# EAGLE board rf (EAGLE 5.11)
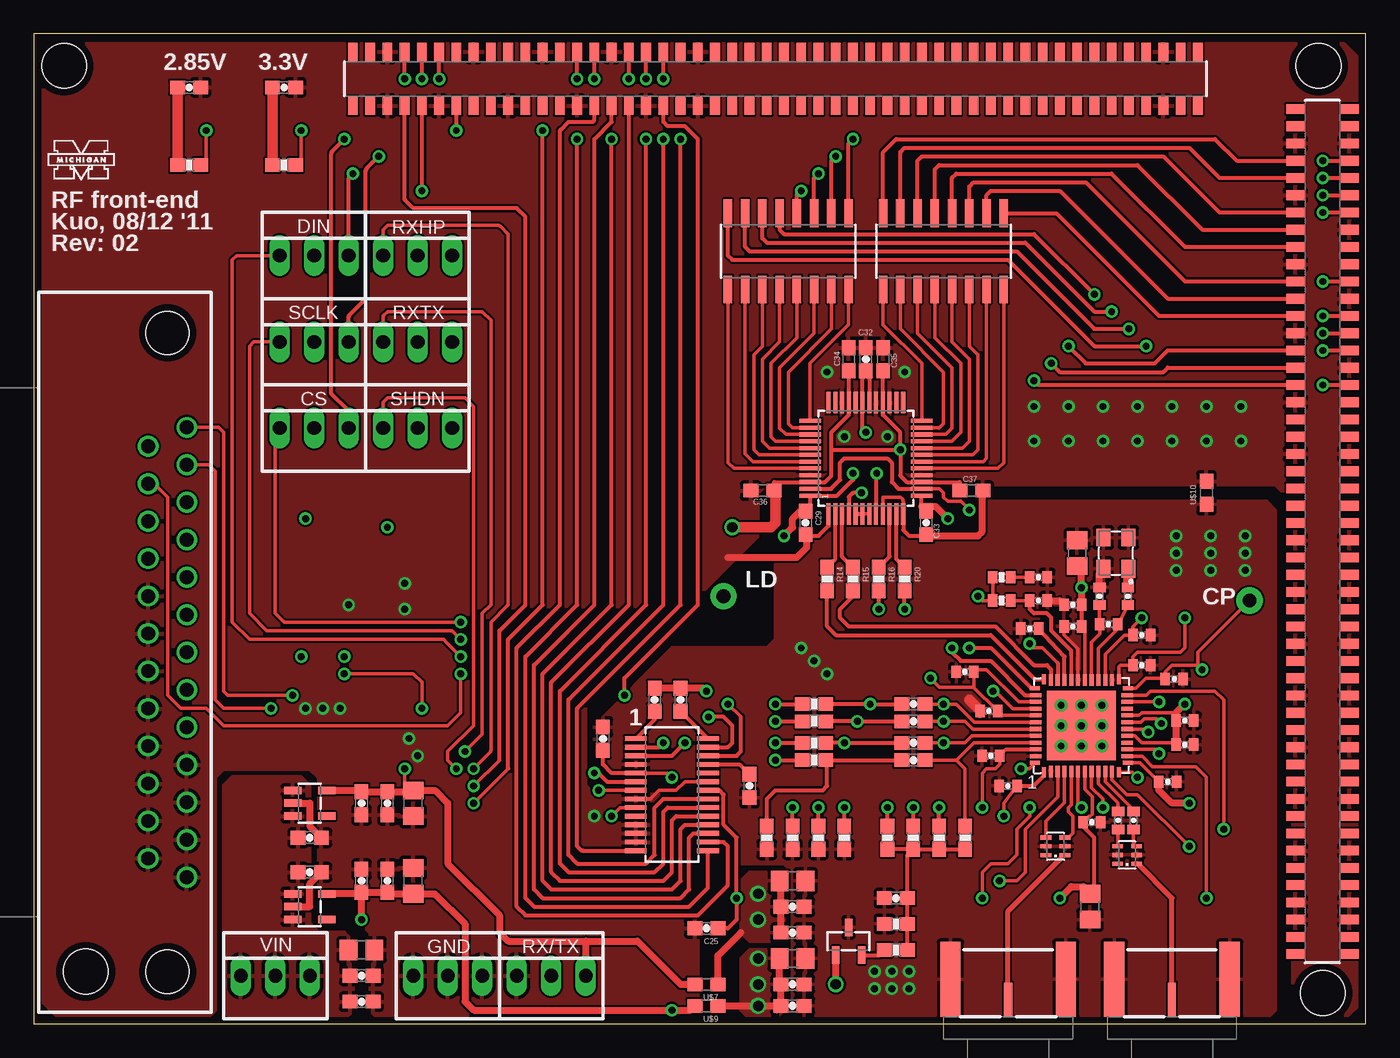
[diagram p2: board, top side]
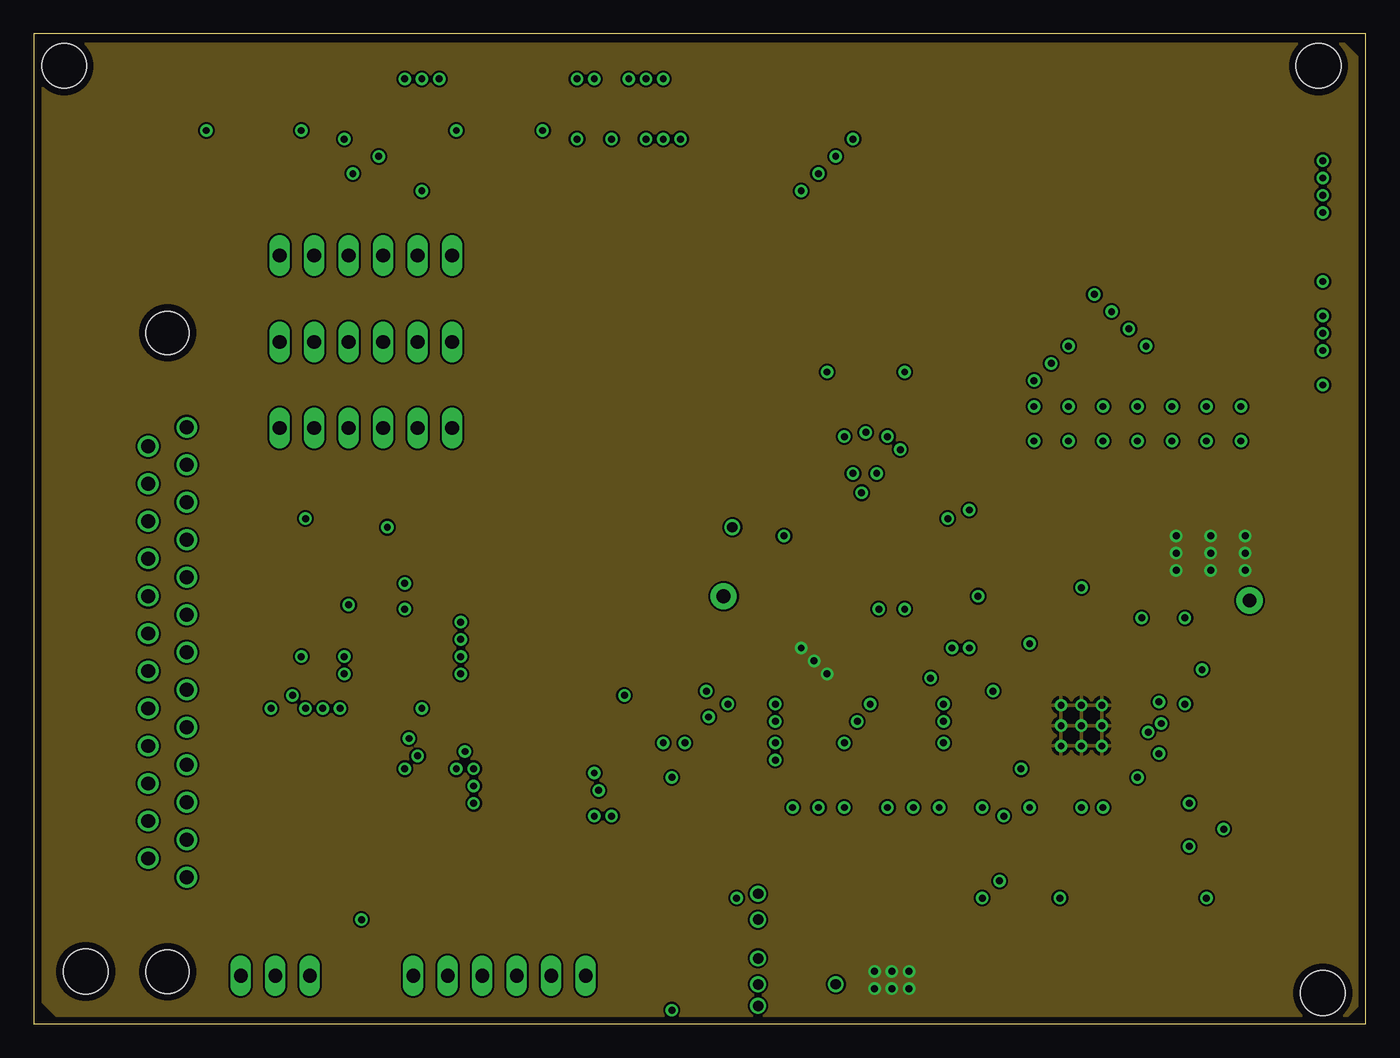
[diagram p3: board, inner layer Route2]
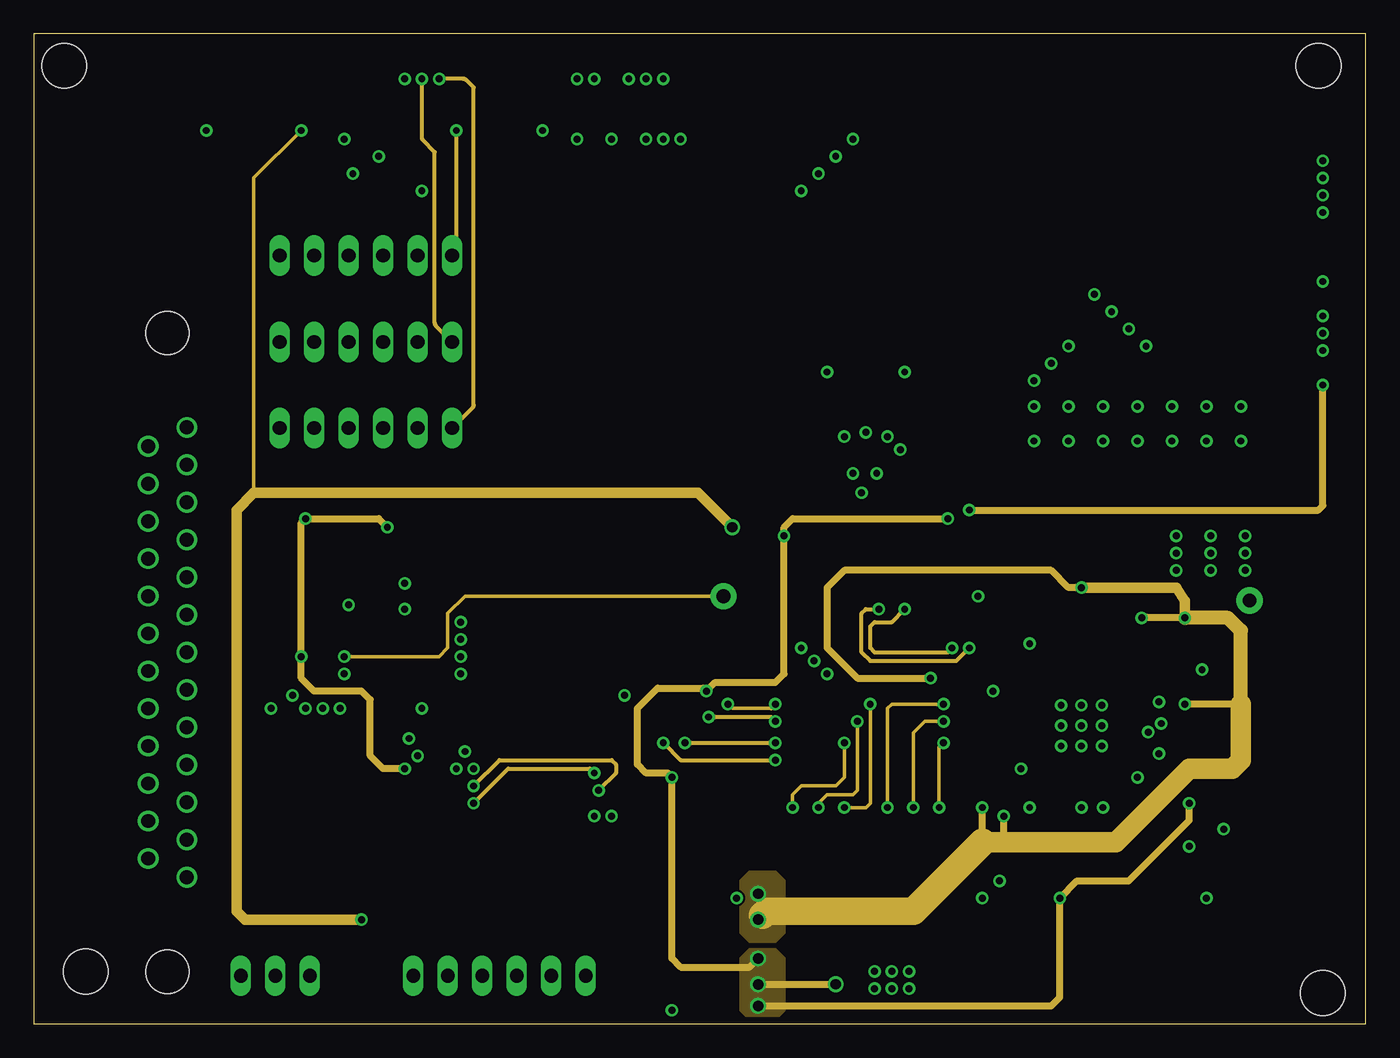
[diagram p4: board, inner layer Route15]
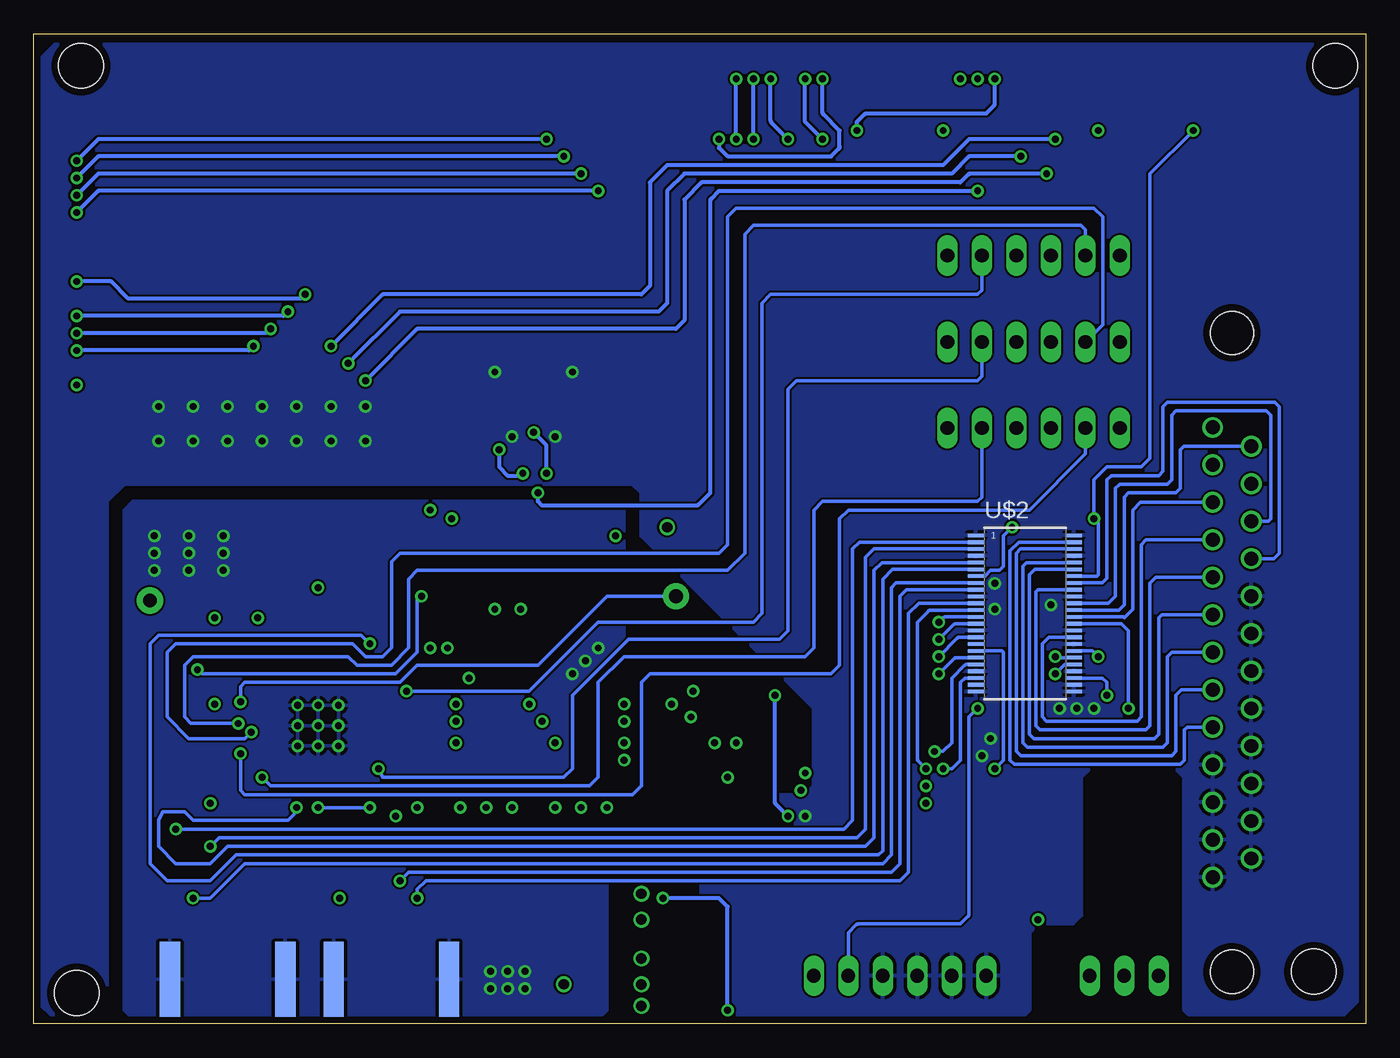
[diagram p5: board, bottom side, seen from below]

Size 98.08 x 72.87 mm. Coordinates in mm from the lower left corner, seen from the top.
Outline: 0,0 98.08,0 98.08,72.87 0,72.87 0,0
Copper layers (1+2*15+16): Top 0.0178mm / dielectric 0.3048mm / Route2 0.0356mm / dielectric 0.7112mm / Route15 0.0356mm / dielectric 0.3048mm / Bottom 0.0178mm
Design rules "SSC-EAGLE-4Lyr_v1.0.0.3 *": minimum track width 6mil, minimum drill 8mil, track to track 6mil, track to pad 6mil, pad to pad 6mil, via to via 6mil, smd to smd 6mil, copper to edge 20mil, drill to drill 16mil, minimum pad ring 8mil, minimum via ring 8mil, stop-mask expansion 3mil, vias tented up to drill 0mil, thermal gap 10mil

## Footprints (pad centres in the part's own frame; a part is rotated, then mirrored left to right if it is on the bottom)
0402-CAP = smd 0.7 x 0.9: 1 -0.65,0; 2 0.65,0
C0805 = smd 1.3 x 1.5: 1 -0.95,0; 2 0.95,0
0603-CAP = smd 1.1 x 1: 1 -0.85,0; 2 0.85,0
C0603 = smd 1.1 x 1: 1 -0.85,0; 2 0.85,0
22-23-2031 = drill 1 long: 1 -2.54,0; 2 0,0; 3 2.54,0
STAND-OFF = hole 3.302: 0,0
CLP-150 = smd 0.711 x 1.35: P$1 -31.115,1.99; P$2 -31.115,-1.99; P$3 -29.845,1.99; P$4 -29.845,-1.99; P$5 -28.575,1.99; P$6 -28.575,-1.99; P$7 -27.305,1.99; P$8 -27.305,-1.99; P$9 -26.035,1.99; P$10 -26.035,-1.99; P$11 -24.765,1.99; P$12 -24.765,-1.99; P$13 -23.495,1.99; P$14 -23.495,-1.99; P$15 -22.225,1.99; P$16 -22.225,-1.99; P$17 -20.955,1.99; P$18 -20.955,-1.99; P$19 -19.685,1.99; P$20 -19.685,-1.99; P$21 -18.415,1.99; P$22 -18.415,-1.99; P$23 -17.145,1.99; P$24 -17.145,-1.99; P$25 -15.875,1.99; P$26 -15.875,-1.99; P$27 -14.605,1.99; P$28 -14.605,-1.99; P$29 -13.335,1.99; P$30 -13.335,-1.99; P$31 -12.065,1.99; P$32 -12.065,-1.99; P$33 -10.795,1.99; P$34 -10.795,-1.99; P$35 -9.525,1.99; P$36 -9.525,-1.99; P$37 -8.255,1.99; P$38 -8.255,-1.99; P$39 -6.985,1.99; P$40 -6.985,-1.99; P$41 -5.715,1.99; P$42 -5.715,-1.99; P$43 -4.445,1.99; P$44 -4.445,-1.99; P$45 -3.175,1.99; P$46 -3.175,-1.99; P$47 -1.905,1.99; P$48 -1.905,-1.99; P$49 -0.635,1.99; P$50 -0.635,-1.99; P$51 0.635,1.99; P$52 0.635,-1.99; P$53 1.905,1.99; P$54 1.905,-1.99; P$55 3.175,1.99; P$56 3.175,-1.99; P$57 4.445,1.99; P$58 4.445,-1.99; P$59 5.715,1.99; P$60 5.715,-1.99; P$61 6.985,1.99; P$62 6.985,-1.99; P$63 8.255,1.99; P$64 8.255,-1.99; P$65 9.525,1.99; P$66 9.525,-1.99; P$67 10.795,1.99; P$68 10.795,-1.99; P$69 12.065,1.99; P$70 12.065,-1.99; P$71 13.335,1.99; P$72 13.335,-1.99; P$73 14.605,1.99; P$74 14.605,-1.99; P$75 15.875,1.99; P$76 15.875,-1.99; P$77 17.145,1.99; P$78 17.145,-1.99; P$79 18.415,1.99; P$80 18.415,-1.99; P$81 19.685,1.99; P$82 19.685,-1.99; P$83 20.955,1.99; P$84 20.955,-1.99; P$85 22.225,1.99; P$86 22.225,-1.99; P$87 23.495,1.99; P$88 23.495,-1.99; P$89 24.765,1.99; P$90 24.765,-1.99; P$91 26.035,1.99; P$92 26.035,-1.99; P$93 27.305,1.99; P$94 27.305,-1.99; P$95 28.575,1.99; P$96 28.575,-1.99; P$97 29.845,1.99; P$98 29.845,-1.99; P$99 31.115,1.99; P$100 31.115,-1.99
0402-RES = smd 0.7 x 0.9: 1 -0.65,0; 2 0.65,0
0603-RES = smd 1.1 x 1: 1 -0.85,0; 2 0.85,0
BALUN = smd 0.8 x 0.3: P$1 -0.7,0.65; P$2 -0.7,0; P$3 -0.7,-0.65; P$4 0.7,-0.65; P$5 0.7,0; P$6 0.7,0.65
SOT-5 = smd 1.3 x 0.55: P$1 -1.25,0.95; P$2 -1.25,0; P$3 -1.25,-0.95; P$4 1.25,-0.95; P$5 1.25,0.95
TQFN-48 = smd 5.1 x 5.1: EP 0,0 | smd 0.3 x 0.75: P$1 -2.75,-3.425; P$12 2.75,-3.425; P$25 2.75,3.425; P$36 -2.75,3.425 | smd 0.3 x 0.85: P$2 -2.25,-3.375; P$3 -1.75,-3.375; P$4 -1.25,-3.375; P$5 -0.75,-3.375; P$6 -0.25,-3.375; P$7 0.25,-3.375; P$8 0.75,-3.375; P$9 1.25,-3.375; P$10 1.75,-3.375; P$11 2.25,-3.375; P$26 2.25,3.375; P$27 1.75,3.375; P$28 1.25,3.375; P$29 0.75,3.375; P$30 0.25,3.375; P$31 -0.25,3.375; P$32 -0.75,3.375; P$33 -1.25,3.375; P$34 -1.75,3.375; P$35 -2.25,3.375 | smd 0.75 x 0.3: P$13 3.425,-2.75; P$24 3.425,2.75; P$37 -3.425,2.75; P$48 -3.425,-2.75 | smd 0.85 x 0.3: P$14 3.375,-2.25; P$15 3.375,-1.75; P$16 3.375,-1.25; P$17 3.375,-0.75; P$18 3.375,-0.25; P$19 3.375,0.25; P$20 3.375,0.75; P$21 3.375,1.25; P$22 3.375,1.75; P$23 3.375,2.25; P$38 -3.375,2.25; P$39 -3.375,1.75; P$40 -3.375,1.25; P$41 -3.375,0.75; P$42 -3.375,0.25; P$43 -3.375,-0.25; P$44 -3.375,-0.75; P$45 -3.375,-1.25; P$46 -3.375,-1.75; P$47 -3.375,-2.25 | drill 0.5 round: P$49 0,0; P$50 0,1.5; P$51 1.5,1.5; P$52 1.5,0; P$53 -1.5,1.5; P$54 -1.5,0; P$55 0,-1.5; P$56 1.5,-1.5; P$57 -1.5,-1.5
TSSOP-48 = smd 1.2 x 0.27: P$1 -3.6,5.75; P$2 -3.6,5.25; P$3 -3.6,4.75; P$4 -3.6,4.25; P$5 -3.6,3.75; P$6 -3.6,3.25; P$7 -3.6,2.75; P$8 -3.6,2.25; P$9 -3.6,1.75; P$10 -3.6,1.25; P$11 -3.6,0.75; P$12 -3.6,0.25; P$13 -3.6,-0.25; P$14 -3.6,-0.75; P$15 -3.6,-1.25; P$16 -3.6,-1.75; P$17 -3.6,-2.25; P$18 -3.6,-2.75; P$19 -3.6,-3.25; P$20 -3.6,-3.75; P$21 -3.6,-4.25; P$22 -3.6,-4.75; P$23 -3.6,-5.25; P$24 -3.6,-5.75; P$25 3.6,-5.75; P$26 3.6,-5.25; P$27 3.6,-4.75; P$28 3.6,-4.25; P$29 3.6,-3.75; P$30 3.6,-3.25; P$31 3.6,-2.75; P$32 3.6,-2.25; P$33 3.6,-1.75; P$34 3.6,-1.25; P$35 3.6,-0.75; P$36 3.6,-0.25; P$37 3.6,0.25; P$38 3.6,0.75; P$39 3.6,1.25; P$40 3.6,1.75; P$41 3.6,2.25; P$42 3.6,2.75; P$43 3.6,3.25; P$44 3.6,3.75; P$45 3.6,4.25; P$46 3.6,4.75; P$47 3.6,5.25; P$48 3.6,5.75
SMA-SMD = smd 1.5 x 5.5: P$1 -4.25,-0.375; P$2 4.25,-0.375 | smd 1.5 x 5.5 bottom: P$3 4.25,-0.375; P$4 -4.25,-0.375 | smd 0.6 x 2.5: SIGNAL 0,1.125
CX3225SB = smd 1.3 x 1.05: GND 1.15,-0.925; GND2 -1.15,0.925; HOT -1.15,-0.925; HOT2 1.15,0.925
QSOP = smd 1.6 x 0.356: P$1 -2.655,4.128; P$2 -2.655,3.493; P$3 -2.655,2.857; P$4 -2.655,2.223; P$5 -2.655,1.587; P$6 -2.655,0.953; P$7 -2.655,0.318; P$8 -2.655,-0.318; P$9 -2.655,-0.953; P$10 -2.655,-1.587; P$11 -2.655,-2.223; P$12 -2.655,-2.857; P$13 -2.655,-3.493; P$14 -2.655,-4.128; P$15 2.655,-4.128; P$16 2.655,-3.493; P$17 2.655,-2.857; P$18 2.655,-2.223; P$19 2.655,-1.587; P$20 2.655,-0.953; P$21 2.655,-0.318; P$22 2.655,0.318; P$23 2.655,0.953; P$24 2.655,1.587; P$25 2.655,2.223; P$26 2.655,2.857; P$27 2.655,3.493; P$28 2.655,4.128
0603 = smd 1.1 x 1: 1 -0.85,0; 2 0.85,0
SOT-3 = smd 0.55 x 1.28: P$1 -0.95,-1.015; P$2 0.95,-1.015; P$3 0,1.015
SOIC-16 = smd 2.03 x 0.63: P$1 -2.8,4.445; P$2 -2.8,3.175; P$3 -2.8,1.905; P$4 -2.8,0.635; P$5 -2.8,-0.635; P$6 -2.8,-1.905; P$7 -2.8,-3.175; P$8 -2.8,-4.445; P$9 2.8,-4.445; P$10 2.8,-3.175; P$11 2.8,-1.905; P$12 2.8,-0.635; P$13 2.8,0.635; P$14 2.8,1.905; P$15 2.8,3.175; P$16 2.8,4.445
LQFP(ST-48) = smd 1.6 x 0.3: P$1 -4.1,2.75; P$2 -4.1,2.25; P$3 -4.1,1.75; P$4 -4.1,1.25; P$5 -4.1,0.75; P$6 -4.1,0.25; P$7 -4.1,-0.25; P$8 -4.1,-0.75; P$9 -4.1,-1.25; P$10 -4.1,-1.75; P$11 -4.1,-2.25; P$12 -4.1,-2.75; P$25 4.1,-2.75; P$26 4.1,-2.25; P$27 4.1,-1.75; P$28 4.1,-1.25; P$29 4.1,-0.75; P$30 4.1,-0.25; P$31 4.1,0.25; P$32 4.1,0.75; P$33 4.1,1.25; P$34 4.1,1.75; P$35 4.1,2.25; P$36 4.1,2.75 | smd 0.3 x 1.6: P$13 -2.75,-4.1; P$14 -2.25,-4.1; P$15 -1.75,-4.1; P$16 -1.25,-4.1; P$17 -0.75,-4.1; P$18 -0.25,-4.1; P$19 0.25,-4.1; P$20 0.75,-4.1; P$21 1.25,-4.1; P$22 1.75,-4.1; P$23 2.25,-4.1; P$24 2.75,-4.1; P$37 2.75,4.1; P$38 2.25,4.1; P$39 1.75,4.1; P$40 1.25,4.1; P$41 0.75,4.1; P$42 0.25,4.1; P$43 -0.25,4.1; P$44 -0.75,4.1; P$45 -1.25,4.1; P$46 -1.75,4.1; P$47 -2.25,4.1; P$48 -2.75,4.1
DB25 = drill 1.02 round: P$1 -16.56,1.42; P$2 -13.8,1.42; P$3 -11.04,1.42; P$4 -8.28,1.42; P$5 -5.52,1.42; P$6 -2.76,1.42; P$7 0,1.42; P$8 2.76,1.42; P$9 5.52,1.42; P$10 8.28,1.42; P$11 11.04,1.42; P$12 13.8,1.42; P$13 16.56,1.42; P$14 -15.18,-1.42; P$15 -12.42,-1.42; P$16 -9.66,-1.42; P$17 -6.9,-1.42; P$18 -4.14,-1.42; P$19 -1.38,-1.42; P$20 1.38,-1.42; P$21 4.14,-1.42; P$22 6.9,-1.42; P$23 9.66,-1.42; P$24 12.42,-1.42; P$25 15.18,-1.42 | hole 3.18: -23.52,0; 23.52,0

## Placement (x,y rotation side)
C1  100p  [0402-CAP]  71.75,17.5 180 top
C2  100p  [0402-CAP]  77.91,14.83 0 top
C3  10u  [C0805]  77.79,8.61 270 top
C4  1.5p  [0402-CAP]  79.85,14.96 270 top
C5  1.5p  [0402-CAP]  80.99,14.96 270 top
C6  100p  [0402-CAP]  83.5,17.82 0 top
C7  100p  [0402-CAP]  84.77,20.55 0 top
C8  10n  [0402-CAP]  84.77,22.33 0 top
C9  10n  [0402-CAP]  81.6,26.39 0 top
C10  10n  [0402-CAP]  81.6,28.61 0 top
C11  100p  [0402-CAP]  76.52,29.25 180 top
C12  100n  [0402-CAP]  76.52,30.84 180 top
C13  10u  [C0805]  76.83,34.65 270 top
C14  10n  [0402-CAP]  68.58,25.91 180 top
C15  10n  [0402-CAP]  70.33,23.03 180 top
C16  100p  [0402-CAP]  70.48,19.72 180 top
C17  68p  [0402-CAP]  73.98,31.15 180 top
C18  2.2n  [0402-CAP]  73.98,32.87 180 top
C19  100p  [0402-CAP]  83.98,25.37 0 top
C20  33p  [0402-CAP]  79.15,29.41 0 top
C21  18p  [0402-CAP]  78.49,31.47 90 top
C22  1n  [0402-CAP]  80.58,31.47 90 top
C23  100n  [0402-CAP]  73.34,29.09 180 top
C24  0.1u  [0603-CAP]  52.7,17.5 270 top
C25  0.1u  [0603-CAP]  49.53,7.02 180 top
C26  10u  [C0805]  55.88,10.52 0 top
C27  0.1u  [0603-CAP]  26.04,10.52 90 top
C28  0.1u  [0603-CAP]  41.91,20.99 270 top
C29  0.1u  [0603-CAP]  56.83,36.87 270 top
C30  0.1u  [0603-CAP]  47.62,23.85 270 top
C31  1u  [0603-CAP]  24.13,10.52 90 top
C32  0.1u  [0603-CAP]  61.28,48.93 90 top
C33  0.1u  [0603-CAP]  65.72,36.87 270 top
C34  0.1u  [C0603]  60.01,48.93 90 top
C35  0.1u  [C0603]  62.55,48.93 90 top
C36  0.1u  [C0603]  53.66,39.25 180 top
C37  0.1u  [C0603]  69.06,39.25 0 top
C38  0.01u  [0603-CAP]  64.77,22.26 0 top
C39  0.1u  [0603-CAP]  24.13,16.23 270 top
C40  1u  [0603-CAP]  26.04,16.23 270 top
C41  10u  [C0805]  24.13,5.44 0 top
C42  0.1u  [0603-CAP]  45.72,23.85 270 top
C43  0.1u  [0603-CAP]  63.5,9.25 180 top
C44  0.01u  [0603-CAP]  64.77,23.53 0 top
C45  0.01u  [0603-CAP]  64.77,19.41 180 top
C46  0.01u  [0603-CAP]  64.77,20.68 180 top
C47  10u  [C0805]  27.94,16.23 270 top
C48  10u  [C0805]  55.88,4.8 0 top
C49  10u  [C0805]  27.94,10.52 90 top
C50  0.1u  [0603-CAP]  18.41,68.94 0 top
C51  0.1u  [0603-CAP]  11.43,68.94 0 top
C72  0.1u  [0603-CAP]  24.13,3.53 0 top
C73  1u  [0603-CAP]  24.13,1.63 0 top
C74  0.1u  [0603-CAP]  20.32,11.15 0 top
C75  0.1u  [0603-CAP]  20.32,13.69 0 top
C78  0.1u  [0603-CAP]  55.88,1.31 0 top
C79  1u  [0603-CAP]  55.88,2.9 0 top
C80  0.1u  [0603-CAP]  55.88,8.61 0 top
C81  1u  [0603-CAP]  55.88,6.71 0 top
CS  22-23-2031  [22-23-2031]  20.64,43.85 0 top
DIN  22-23-2031  [22-23-2031]  20.64,56.55 0 top
GND  22-23-2031  [22-23-2031]  30.48,3.53 0 top
JP4  STAND-OFF  [STAND-OFF]  2.22,70.52 0 top
JP5  STAND-OFF  [STAND-OFF]  3.81,3.85 0 top
JP6  STAND-OFF  [STAND-OFF]  94.61,70.52 0 top
JP7  STAND-OFF  [STAND-OFF]  94.93,2.26 0 top
P1  DEV_CLP-150  [CLP-150]  54.61,69.57 0 top
P2  DEV_CLP-150  [CLP-150]  94.91,36.23 270 top
R1  750  [0402-RES]  71.28,31.15 180 top
R2  1.2k  [0402-RES]  71.28,32.87 0 top
R3  75  [0603-RES]  57.47,22.26 0 top
R4  75  [0603-RES]  57.78,13.69 90 top
R5  75  [0603-RES]  57.47,23.53 180 top
R6  75  [0603-RES]  59.69,13.69 90 top
R7  75  [0603-RES]  57.47,19.41 0 top
R8  75  [0603-RES]  57.47,20.68 0 top
R9  75  [0603-RES]  55.88,13.69 90 top
R10  75  [0603-RES]  53.98,13.69 90 top
R11  3.3k  [0603-RES]  64.77,13.69 270 top
R12  270  [0603-RES]  63.5,5.44 0 top
R13  1k  [0603-RES]  63.5,7.34 0 top
R14  0  [0603-RES]  58.42,32.74 270 top
R15  0  [0603-RES]  60.33,32.74 270 top
R16  0  [0603-RES]  62.23,32.74 270 top
R17  3.3k  [0603-RES]  62.87,13.69 270 top
R18  3.3k  [0603-RES]  68.58,13.69 270 top
R19  3.3k  [0603-RES]  66.67,13.69 270 top
R20  0  [0603-RES]  64.14,32.74 270 top
R21  3.3k  [0603-RES]  18.41,63.22 0 top
R22  3.3k  [0603-RES]  11.43,63.22 0 top
RX/TX  22-23-2031  [22-23-2031]  38.1,3.53 0 top
RXHP  22-23-2031  [22-23-2031]  28.26,56.55 0 top
RXTX  22-23-2031  [22-23-2031]  28.26,50.2 0 top
SCLK  22-23-2031  [22-23-2031]  20.64,50.2 0 top
SHDN  22-23-2031  [22-23-2031]  28.26,43.85 0 top
T1  TDK_CHIP_BALUN  [BALUN]  75.25,13.06 180 top
T2  TDK_CHIP_BALUN  [BALUN]  80.52,12.42 180 top
U1  REG102  [SOT-5]  20.32,16.23 0 top
U2  REG102  [SOT-5]  20.32,8.61 0 top
U$1  MAX2831  [TQFN-48]  77.15,21.95 0 top
U$2  SN74LVTH16244A  [TSSOP-48]  25.08,30.2 0 bottom
U$3  J658-ND  [SMA-SMD]  71.75,2.9 180 top
U$4  J658-ND  [SMA-SMD]  83.82,2.9 180 top
U$5  CX3225SB  [CX3225SB]  79.69,34.65 90 top
U$6  MAX5189BEEI+  [QSOP]  46.99,16.87 0 top
U$7  [0603]  49.53,2.9 180 top
U$8  [UMICH]  0.95,61.95 0 top
U$9  [0603]  49.53,1.31 180 top
U$10  [0603]  86.36,39.09 90 top
U$11  MAX6601  [SOT-3]  60.01,6.07 0 top
U$13  CTS766  [SOIC-16]  55.56,56.87 90 top
U$14  CTS766  [SOIC-16]  66.99,56.87 90 top
U$21  AD9288  [LQFP(ST-48)]  61.28,41.63 90 top
VIN  22-23-2031  [22-23-2031]  17.78,3.53 0 top
X1  [DB25]  9.84,27.34 270 top

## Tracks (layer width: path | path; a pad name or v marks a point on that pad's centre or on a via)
AGND  (via drill 0.51)
  Top 0.254: C11.2 75.87,28.63 76.9,27.59 U$1.P$31
  Top 0.406: C15.2 69.68,23.07
  Top 0.508: C17.1 75.55,31.15 C12.2 | C21.2 78.49,33.21 U$5.GND2
  Top 0.762: 69.68,23.07 68.9,23.85
  other vias: 84.14,35.92 86.68,35.92 89.22,35.92 89.22,34.65 86.68,34.65 84.14,34.65 84.14,33.38 86.68,33.38 89.22,33.38 61.91,3.85 63.18,3.85 64.45,3.85 64.45,2.58 63.18,2.58 61.91,2.58 56.52,27.66 57.47,26.71 58.42,25.76
  pour Top: 41.27,21.95 41.27,18.77 41.91,18.14 49.53,18.14 50.16,17.5 50.16,12.42 50.8,11.79 55.24,11.79 55.88,11.15 55.88,0.99 56.52,0.36 90.81,0.36 91.44,0.99 91.44,37.82 90.81,38.46 74.61,38.46 74.61,24.8 74.93,25.12 80.01,25.12 80.33,24.8 80.33,19.09 80.01,18.77 74.3,18.77 73.98,19.09 73.98,38.46 55.24,38.46 54.61,37.82 54.61,28.3 53.98,27.66 46.99,27.66
  pour Route2: 1.91,0.36 96.52,0.36 97.16,0.99 97.79,1.63 97.79,70.84 96.52,72.11 1.91,72.11 0.64,70.84 0.64,1.63
  pour Bottom: 41.27,21.95 41.27,18.77 41.91,18.14 49.53,18.14 50.16,17.5 50.16,12.42 50.8,11.79 55.24,11.79 55.88,11.15 55.88,0.99 56.52,0.36 90.81,0.36 91.44,0.99 91.44,37.82 90.81,38.46 55.24,38.46 54.61,37.82 54.61,28.3 53.98,27.66 46.99,27.66
  pour Top: 74.93,38.46 74.93,30.2 74.61,29.88 73.66,29.88 73.34,30.2 73.34,38.46
AVDD1.2
  Top 0.305: U$11.P$2 62.27,5.06 R12.1
AVDD2.85  (via drill 0.51, 0.76)
  Top 0.254: U$1.P$17 81.08,21.2 81.6,20.68 84,20.68 | C7.1 84,20.99 | U$1.P$20 81.39,22.7 81.6,22.9 84.11,22.9 84.12,22.88 C8.1 84.07,22.33 | U$1.P$25 79.9,26.28 80.01,26.39 C9.1 80.95,27.01 81.28,27.34 84.45,27.34 84.77,27.66 v84.77,29.88 | U$1.P$27 78.9,27.19 80.33,28.61 C10.1 80.95,29.23 v81.6,29.88 | U$1.P$30 77.4,29.01 C11.1 | C16.1 71.12,19.71 | C16.1 71.14,19.1 70.8,18.77 70.17,18.77 69.85,18.45 v69.85,15.91 | C16.1 71.61,20.2 | v71.44,15.28 71.44,16.23 71.45,16.23 C1.1 | U$1.P$39 72.55,23.7 70.17,26.07 69.39,26.07 C14.1 | C14.1 69.39,25.76 | C14.1 69.22,25.9 | C15.1 70.98,23.04 | U$1.P$41 71.31,22.7 C15.1 | 69.22,24.79 C15.1 | 69.22,24.79 66.69,24.79 v66.04,25.44 | C14.1 69.23,24.8 69.22,24.79
  Top 0.305: 71.61,20.2 U$1.P$46 | C1.1 73.66,17.5 74.4,18.24 U$1.P$1 | C7.1 84,20.68 | C12.1 C11.1
  Top 0.508: 84.12,20.37 C7.1 C8.1 | C81.1 C80.1 55.03,10.42 C26.1 | C12.1 77.15,30.85 v77.15,32.11 77.15,33.38 C13.2 | U$7.1 50.38,5.02 52.07,6.71 | v84.77,23.53 84.12,22.88
  Route15 0.508: v84.77,29.88 v81.6,29.88 | v66.04,25.44 60.64,25.44 58.42,27.66 58.42,32.11 59.69,33.38 74.93,33.38 76.2,32.11 v77.15,32.11 | v71.44,15.28 71.44,13.69 71.75,13.37 | 69.85,13.37 v69.85,15.91 | 88.9,23.53 v84.77,23.53
  Route15 0.762: v77.15,32.11 84.14,32.11 84.77,31.15 v84.77,29.88
  Route15 1.016: v84.77,29.88 87.95,29.88 88.9,28.93 88.9,23.53
  Route15 1.524: 69.85,13.37 71.75,13.37 79.69,13.37 85.09,18.77 88.27,18.77 88.9,19.41 88.9,23.53
  Route15 2.032: 69.85,13.37 64.77,8.29 53.98,8.29 53.66,7.98
  other vias: 53.34,9.56 53.34,7.66
  pour Top: 55.24,10.52 55.24,6.71 54.61,6.07 52.7,6.07 52.07,6.71 52.07,10.52 52.7,11.15 54.61,11.15
  pour Route15: 55.24,10.52 55.24,6.71 54.61,6.07 52.7,6.07 52.07,6.71 52.07,10.52 52.7,11.15 54.61,11.15
AVDD3.3  (via drill 0.51, 0.76)
  Top 0.254: U$1.P$13 81.47,19.2 C6.1 | U$1.P$7 77.4,17.25 77.95,16.71 77.95,15.44 77.79,15.28 77.71,15.28 C2.1 | U$6.P$5 46.67,18.45 v46.99,18.14
  Top 0.305: U$21.P$30 61.53,47.52 C32.1 61.03,47.52 U$21.P$31 61.03,43.79 v61.28,43.54 | U$21.P$13 65.38,38.06 C33.1 | C29.1 57.18,38.06 U$21.P$48 59.16,38.88 60.33,40.04 v60.33,40.52 | 77.26,10.08 C3.1 78.11,9.88 78.11,13.69 77.26,14.53 C2.1 | C28.2 41.91,19.09 42.55,18.45 U$6.P$5
  Top 0.508: C78.1 54.71,0.99 | C48.1 54.93,3 C79.1 C78.1 | U$9.1 C78.1 | U$11.P$1 v59.06,2.9 v59.05,2.9 | 77.26,10.08 76.4,10.08 v75.56,9.25 | C6.1 82.85,17.2 83.82,16.23 v85.09,16.23 | C29.1 56.41,37.72 55.88,37.19 55.88,36.55 v55.24,35.92 | 65.38,38.06 66.43,38.06 v67.31,37.19 | v49.53,24.49 49.31,24.7 C30.1 C42.1
  Route15 0.508: v59.06,2.9 v53.34,2.9 | v85.09,16.23 85.09,14.96 80.64,10.52 76.83,10.52 v75.56,9.25 75.56,1.94 74.93,1.31 v53.34,1.31 | v67.31,37.19 55.88,37.19 55.24,36.55 v55.24,35.92 55.24,25.76 54.61,25.12 50.16,25.12 v49.53,24.49 49.31,24.7 45.94,24.7 44.45,23.22 44.45,19.09 45.09,18.45 46.67,18.45 v46.99,18.14 46.99,4.8 47.62,4.17 52.7,4.17 v53.34,4.8
  Bottom 0.305: v60.33,40.52 60.33,42.58 v61.28,43.54
  pour Top: 55.24,4.8 55.24,0.99 54.61,0.36 52.7,0.36 52.07,0.99 52.07,4.8 52.7,5.44 54.61,5.44
  pour Route15: 55.24,4.8 55.24,0.99 54.61,0.36 52.7,0.36 52.07,0.99 52.07,4.8 52.7,5.44 54.61,5.44
B1  (via drill 0.51)
  Top 0.254: v87.63,14.33 87.63,23.85 87,24.49 82.23,24.49 81.94,24.2 U$1.P$23
  Bottom 0.254: U$2.P$2 37.3,35.45 37.78,34.96 37.78,14.96 38.42,14.33 v87.63,14.33
B2  (via drill 0.51)
  Top 0.254: U$1.P$11 79.4,17.95 80.49,16.87 81.28,16.87 v85.09,13.06
  Bottom 0.254: v85.09,13.06 84.45,13.69 37.47,13.69 36.83,14.33 36.83,34.33 36.21,34.95 U$2.P$3
B3  (via drill 0.51)
  Top 0.254: U$1.P$8 77.9,17.39 78.74,16.55 v78.74,15.91
  Bottom 0.254: v78.74,15.91 78.74,15.6 79.38,14.96 86.36,14.96 87,15.6 88.58,15.6 88.9,14.96 88.9,13.06 87.63,11.79 85.09,11.79 83.82,13.06 36.83,13.06 36.2,13.69 36.2,33.38 35.62,33.95 U$2.P$5
B4  (via drill 0.51)
  Top 0.254: 75.4,26.55 74.3,27.66 73.66,27.66 v73.34,27.98
  Top 0.305: 75.4,26.55 U$1.P$34
  Bottom 0.254: v73.34,27.98 73.98,28.61 88.9,28.61 89.53,27.98 89.53,11.79 88.27,10.52 85.09,10.52 83.19,12.42 35.88,12.42 35.56,12.74 35.56,32.74 34.85,33.45 U$2.P$6
B5  (via drill 0.51)
  Top 0.254: U$1.P$14 81.62,19.7 82.39,18.93 85.57,18.93 86.36,18.14 v86.36,9.25
  Bottom 0.254: v86.36,9.25 85.09,9.25 82.55,11.79 35.56,11.79 34.92,12.42 34.92,32.11 34.58,32.45 U$2.P$8
B6  (via drill 0.51)
  Top 0.254: U$1.P$3 75.4,16.7 73.03,14.33 73.03,11.15 72.39,10.52 v71.12,10.52
  Bottom 0.254: v71.12,10.52 70.48,11.15 34.92,11.15 34.29,11.79 34.29,31.47 33.81,31.95 U$2.P$9
B7  (via drill 0.51)
  Top 0.254: v69.85,9.25 69.85,11.15 70.48,11.79 71.75,11.79 72.39,12.42 72.39,14.33 73.34,15.28 v73.34,15.91 | U$1.P$6 76.9,16.16 v77.15,15.91
  Bottom 0.254: v73.34,15.91 v77.15,15.91 | v69.85,9.25 69.85,9.88 69.22,10.52 34.29,10.52 33.66,11.15 33.66,30.2 32.91,30.95 U$2.P$11
CLK  (via drill 0.51)
  Top 0.254: U$21.P$14 66.7,39.38 66.99,39.09 66.99,38.77 67.31,38.46 68.26,38.46 v68.9,37.82
  Top 0.305: U$21.P$47 58.71,39.38 59.37,40.04 59.37,41.31 59.69,41.63 62.87,41.63 63.18,41.31 63.18,39.88 63.69,39.38 U$21.P$14 | v94.93,47.03 P2.P$33
  Route15 0.508: v94.93,47.03 94.93,38.14 94.61,37.82 v68.9,37.82
CS_B  (via drill 0.51)
  Top 0.254: U$1.P$15 82.55,20.2 v82.87,19.88
  Bottom 0.254: v82.87,19.88 82.87,17.18 82.55,16.87 53.98,16.87 53.34,17.5 53.34,25.12 52.7,25.76 39.37,25.76 38.73,26.39 38.73,37.19 38.1,37.82 24.77,37.82 20.64,41.95 CS.2
DGND  (via drill 0.51)
  Top 0.254: U$21.P$12 64.03,38.46 arc45 63.95,38.64 63.82,38.77 62.55,38.77 arc45 62.53,38.72 U$21.P$9 | U$6.P$23 47.94,17.82 47.31,17.18 46.04,17.18 45.4,16.55
  Top 0.305: U$6.P$8 45.4,16.55 | U$21.P$1 58.53,36.66 57.78,35.92 56.94,35.92 C29.2 | U$21.P$12 64.03,36.34 64.45,35.92 65.62,35.92 C33.2
  Top 0.508: U2.P$2 20.32,8.61 20.32,10.3 C74.2 | U1.P$2 20.32,16.23 20.32,14.54 C75.2 | 56.94,35.92 56.94,35.07 56.2,34.33 51.12,34.33 | 65.62,35.92 69.53,35.92 69.85,36.23 69.85,39.19 C37.2
  other vias: 59.69,43.22 62.87,43.22 58.42,47.98 64.14,47.98 41.27,15.28 20,23.22 21.27,23.22 22.54,23.22 27.3,32.42 27.3,30.52 27.62,20.99 28.26,19.72 73.66,45.44 76.2,45.44 78.74,45.44 81.28,45.44 83.82,45.44 86.36,45.44 88.9,45.44 88.9,42.9 86.36,42.9 83.82,42.9 81.28,42.9 78.74,42.9 76.2,42.9 73.66,42.9 23.18,30.84
  pour Top: 0.64,70.84 0.64,1.63 1.91,0.36 12.7,0.36 13.34,0.99 13.34,18.14 13.97,18.77 20.32,18.77 20.95,18.14 20.95,7.98 21.59,7.34 24.13,7.34 24.77,6.71 24.77,0.99 25.4,0.36 48.26,0.36 48.9,0.99 48.9,16.23 48.26,16.87 41.27,16.87 40.64,17.5 40.64,23.22 53.34,35.92 53.34,39.09 53.98,39.73 91.44,39.73 92.71,38.46 92.71,1.63 93.98,0.36 96.52,0.36 97.79,1.63 97.79,70.84 96.52,72.11 1.91,72.11
  pour Bottom: 0.64,70.84 0.64,1.63 1.91,0.36 12.7,0.36 13.34,0.99 13.34,18.14 13.97,18.77 20.32,18.77 20.95,18.14 20.95,7.98 21.59,7.34 24.13,7.34 24.77,6.71 24.77,0.99 25.4,0.36 48.26,0.36 48.9,0.99 48.9,16.23 48.26,16.87 41.27,16.87 40.64,17.5 40.64,23.22 53.34,35.92 53.34,39.09 53.98,39.73 91.44,39.73 92.71,38.46 92.71,1.63 93.98,0.36 96.52,0.36 97.79,1.63 97.79,70.84 96.52,72.11 1.91,72.11
DIN  (via drill 0.51)
  Top 0.254: U$1.P$19 81.53,22.2 81.79,22.45 82.68,22.45 v83.03,22.1
  Bottom 0.254: v83.03,22.1 86.52,22.1 87,22.58 87,26.39 86.36,27.03 74.93,27.03 74.3,26.39 71.75,26.39 70.48,27.66 70.48,32.74 69.85,33.38 46.99,33.38 45.72,34.65 45.72,58.14 45.09,58.78 20.95,58.78 20.64,58.46 DIN.2
DVDD2.85  (via drill 0.51)
  Top 0.254: 27.3,17.08 v27.3,18.77 | v12.7,65.76 12.7,63.64 R22.2
  Top 0.508: U1.P$5 24.03,17.18 C39.1 C40.1 27.3,17.08 27.84,17.08 C47.1 29.53,17.18 30.48,16.23 30.48,11.79 34.29,7.98 34.29,6.71 34.92,6.07 40.64,6.07 | 40.64,6.07 44.45,6.07 47.62,2.9 U$7.2 | 40.64,6.07 RX/TX.3
  Route15 0.508: v27.3,18.77 25.72,18.77 24.77,19.72 24.77,23.85 24.13,24.49 20.64,24.49 19.68,25.44 v19.68,27.03 19.68,36.87 v20,37.19 25.4,37.19 v26.04,36.55
  Bottom 0.254: U$2.P$31 20.11,27.45 v19.68,27.03 | U$2.P$18 26.78,27.45 26.67,27.34 26.67,19.41 v27.3,18.77 | U$2.P$7 28.05,32.95 27.62,33.38 26.99,33.38 26.67,33.69 26.67,35.92 v26.04,36.55 | U$2.P$42 19.79,32.95 19.68,33.06 19.68,36.87 v20,37.19 20,40.04 19.05,41 16.51,41 15.88,41.63 15.88,62.59 v12.7,65.76
DVDD3.3  (via drill 0.51, 0.76)
  Top 0.254: v19.68,65.76 19.68,63.64 R21.2
  Top 0.305: C35.1 62.53,47.75 U$21.P$28 62.53,44.83 63.82,43.54 v63.82,42.27 | C34.1 60.03,47.75 U$21.P$33 60.03,44.83 58.74,43.54 58.74,42.27 | 58.74,42.27 v63.82,42.27 | v63.82,42.27 63.82,40.36 64.3,39.88 U$21.P$15 68.2,39.88 C37.1 | 58.74,42.27 58.74,40.36 58.26,39.88 U$21.P$46 54.51,39.88 C36.1 | U$21.P$8 62.03,40.48 v62.07,40.52 | U$6.P$22 50.48,17.18 50.8,16.87 50.8,14.64 51.75,13.69 v51.75,9.25 51.75,7.66 51.12,7.02 C25.1
  Top 0.508: C31.1 24.02,9.56 | C31.1 C27.1 26.14,9.57 C49.1 29.52,9.57 31.75,7.34 31.75,1.63 32.38,0.99 v46.99,0.99 48.36,0.99 U$9.2 | U2.P$5 24.13,9.56 C31.1 | v24.13,7.66 C31.1
  Top 0.762: v51.44,36.55 54.29,36.55 54.61,36.87 54.61,39.15 C36.1
  Route15 0.254: 16.19,39.09 16.19,62.27 v19.68,65.76
  Route15 0.762: v24.13,7.66 15.56,7.66 14.92,8.29 14.92,37.82 16.19,39.09 48.9,39.09 v51.44,36.55
  Bottom 0.305: v51.75,9.25 47.62,9.25 46.99,8.61 v46.99,0.99 | v63.82,42.27 63.82,41 63.18,40.36 62.23,40.36 v62.07,40.52
F2-200-IO_0  (via drill 0.51)
  Top 0.305: v40.01,69.57 P1.P$27 | U$6.P$14 40.43,12.74 arc-45 40.25,12.81 40.01,13.06 40.01,23.22 47.62,30.84 v47.62,65.13
  Bottom 0.305: v40.01,69.57 40.01,67.14 arc-45 39.93,66.96 38.73,65.76 38.73,64.6 arc45 38.81,64.42 39.37,63.86 46.88,63.86 arc45 47.06,63.93 47.62,64.49 v47.62,65.13
F2-200-IO_1  (via drill 0.51)
  Top 0.305: v41.27,69.57 P1.P$29 | v40.01,65.13 40.01,30.84 36.2,27.03 36.2,9.25 36.83,8.61 48.26,8.61 49.65,9.99 U$6.P$15
  Bottom 0.305: v40.01,65.13 41.27,66.4 v41.27,69.57
F2-200-IO_2
  Top 0.305: U$6.P$16 50.8,13.37 51.12,13.06 51.12,10.2 48.9,7.98 36.2,7.98 35.56,8.61 35.56,27.66 38.73,30.84 38.73,65.66 arc-45 38.81,65.83 39.37,66.4 41.17,66.4 41.2,66.43 arc45 41.27,66.61 P1.P$30
F2-200-IO_3
  Top 0.305: U$6.P$17 48.58,14.01 48.26,13.69 48.26,9.88 47.62,9.25 37.47,9.25 36.83,9.88 36.83,26.39 41.27,30.84 41.27,65.13 42.55,66.4 P1.P$32
F2-200-IO_4  (via drill 0.51)
  Top 0.305: U$6.P$18 47.94,14.64 47.62,14.33 47.62,10.52 46.99,9.88 38.1,9.88 37.47,10.52 37.47,25.76 42.55,30.84 v42.55,65.13 | v43.81,69.57 P1.P$33
  Bottom 0.305: v43.81,69.57 43.81,66.5 arc-45 43.74,66.32 v42.55,65.13
F2-200-IO_5
  Top 0.305: U$6.P$19 47.31,15.28 46.99,14.96 46.99,11.15 46.35,10.52 38.73,10.52 38.1,11.15 38.1,25.12 43.81,30.84 P1.P$34
F2-200-IO_6  (via drill 0.51)
  Top 0.305: U$6.P$20 46.67,15.91 46.35,15.6 46.35,11.79 45.72,11.15 39.37,11.15 38.73,11.79 38.73,24.49 45.09,30.84 v45.09,65.13 | v45.09,69.57 P1.P$35
  Bottom 0.305: v45.09,65.13 v45.09,69.57
F2-200-IO_7  (via drill 0.51)
  Top 0.305: U$6.P$21 46.35,16.55 45.72,15.91 45.72,12.42 45.09,11.79 40.01,11.79 39.37,12.42 39.37,23.85 46.35,30.84 v46.35,65.13 | v46.35,69.57 P1.P$37
  Bottom 0.305: v46.35,65.13 v46.35,69.57
F2-200-IO_8  (via drill 0.51)
  Top 0.254: U$6.P$9 43.18,15.91 v42.55,15.28
  Top 0.305: P1.P$38 46.35,66.4 46.67,66.08 47.94,66.08 48.9,65.13 48.9,30.84 43.81,25.76 43.5,25.44 v43.5,24.17
  Bottom 0.305: v43.5,24.17 43.5,16.23 v42.55,15.28
F2-500_E11
  Top 0.305: U$14.P$15 63.82,64.17 64.14,64.49 85.09,64.49 87.31,62.27 P2.P$10
F2-500_E12
  Top 0.305: 65.09,59.73 U$14.P$14 65.09,63.54 65.41,63.86 83.19,63.86 87.31,59.73 P2.P$14
F2-500_E23
  Top 0.305: U$14.P$13 66.36,62.9 66.67,63.22 81.28,63.22 86.04,58.46 P2.P$16
F2-500_E24
  Top 0.305: U$14.P$12 67.63,62.27 67.94,62.59 79.38,62.59 84.77,57.19 P2.P$18
F2-500_E33
  Top 0.305: U$14.P$11 68.9,61.63 69.22,61.95 77.47,61.95 84.77,54.65 P2.P$22
F2-500_E34
  Top 0.305: U$14.P$10 70.17,61 70.48,61.32 75.56,61.32 83.5,53.38 P2.P$24
F2-500_E35
  Top 0.305: U$14.P$9 75.31,59.67 82.87,52.11 P2.P$26
F2-500_E36  (via drill 0.51)
  Top 0.305: CS.3 23.18,45.02 arc45 23.1,45.2 21.91,46.39 21.91,64.07 arc-45 21.98,64.25 v22.86,65.13 | P2.P$30 83.5,49.57 82.55,48.62 77.47,48.62 v76.2,49.89
  Bottom 0.305: v22.86,65.13 29.21,65.13 31.11,63.22 51.44,63.22 52.7,61.95 52.7,54.33 53.34,53.7 72.39,53.7 v76.2,49.89
F2-500_N1  (via drill 0.51)
  Top 0.305: U$13.P$9 60.01,64.81 v60.33,65.13 | v94.93,63.54 P2.P$7
  Bottom 0.305: v60.33,65.13 93.34,65.13 v94.93,63.54
F2-500_N2  (via drill 0.51)
  Top 0.305: U$13.P$10 58.74,63.54 v59.05,63.86 | v94.93,62.27 P2.P$9
  Bottom 0.305: v59.05,63.86 93.34,63.86 v94.93,62.27
F2-500_N3  (via drill 0.51)
  Top 0.305: U$13.P$11 57.47,62.27 v57.78,62.59 | v94.93,61 P2.P$11
  Bottom 0.305: v57.78,62.59 93.34,62.59 v94.93,61
F2-500_N4  (via drill 0.51)
  Top 0.305: U$13.P$12 56.2,61 v56.52,61.32 | v94.93,59.73 P2.P$13
  Bottom 0.305: v56.52,61.32 93.34,61.32 v94.93,59.73
F2-500_N9  (via drill 0.51)
  Top 0.305: U$13.P$13 54.93,58.46 55.24,58.14 73.66,58.14 v78.11,53.7 | v94.93,54.65 P2.P$21
  Bottom 0.305: v94.93,54.65 92.39,54.65 91.12,53.38 78.42,53.38 v78.11,53.7
F2-500_N10  (via drill 0.51)
  Top 0.305: U$13.P$14 53.66,57.82 53.98,57.51 73.03,57.51 78.11,52.43 v79.38,52.43 | v94.93,52.11 P2.P$25
  Bottom 0.305: v94.93,52.11 79.69,52.11 v79.38,52.43
F2-500_N11  (via drill 0.51)
  Top 0.305: U$13.P$15 52.39,57.19 52.7,56.87 72.39,56.87 78.11,51.16 v80.64,51.16 | v94.93,50.84 P2.P$27
  Bottom 0.305: v94.93,50.84 80.96,50.84 v80.64,51.16
F2-500_N12  (via drill 0.51)
  Top 0.305: U$13.P$16 51.12,56.55 51.44,56.24 71.75,56.24 78.11,49.89 v81.92,49.89 | v94.93,49.57 P2.P$29
  Bottom 0.305: v94.93,49.57 82.23,49.57 v81.92,49.89
F2-500_N36
  Top 0.305: U$14.P$16 62.55,64.17 63.5,65.13 87,65.13 88.58,63.54 P2.P$8
F2-500_W15  (via drill 0.51)
  Top 0.305: SCLK.3 23.18,52 arc-45 23.25,52.18 24.45,53.38 24.45,62.8 arc-45 24.52,62.98 v25.4,63.86 | P2.P$32 83.5,48.3 83.19,47.98 75.56,47.98 v74.93,48.62
  Bottom 0.305: v25.4,63.86 29.21,63.86 30.48,62.59 50.16,62.59 51.44,61.32 51.44,53.06 52.07,52.43 71.12,52.43 v74.93,48.62
F2-500_W16  (via drill 0.51)
  Top 0.305: DIN.3 23.18,62.16 arc-45 23.25,62.34 v23.5,62.59 | P2.P$34 73.98,47.03 v73.66,47.35
  Bottom 0.305: v23.5,62.59 29.11,62.59 arc-45 29.28,62.51 29.84,61.95 48.9,61.95 50.16,60.68 50.16,51.79 50.8,51.16 69.85,51.16 v73.66,47.35
LD  (via drill 0.51, 1.02 pad 1.93)
  Top 0.254: v82.86,23.7 U$1.P$22
  Route15 0.254: v22.86,27.03 29.84,27.03 30.48,27.66 30.48,30.2 31.75,31.47 v50.8,31.47
  Bottom 0.254: v50.8,31.47 55.88,31.47 60.96,26.39 69.85,26.39 71.12,25.12 82.55,25.12 82.87,24.8 v82.87,23.7 v82.86,23.7 | U$2.P$30 22.68,26.95 arc45 v22.86,27.02 v22.86,27.03
MSS_GP_IO_0  (via drill 0.51)
  Top 0.254: v32.38,16.23 34.92,18.77
  Top 0.305: 34.92,18.77 34.92,28.3 37.47,30.84 v37.47,65.76 | v27.3,69.57 P1.P$7 | v41.27,18.45 41.59,18.45 42.23,17.82 U$6.P$6
  Route15 0.305: v32.38,16.23 34.92,18.77 40.96,18.77 v41.27,18.45
  Bottom 0.305: v27.3,69.57 27.3,67.77 arc45 27.38,67.59 27.94,67.03 36.73,67.03 arc-45 36.9,66.96 37.47,66.4 v37.47,65.76
MSS_GP_IO_1  (via drill 0.51)
  Top 0.254: v32.38,17.5 34.29,19.41 | v41.59,17.18 U$6.P$7
  Top 0.305: 34.29,19.41 34.29,28.93 36.2,30.84 36.2,59.41 35.56,60.05 27.94,60.05 27.3,60.68 P1.P$8
  Route15 0.305: v41.59,17.18 42.86,18.45 42.86,19.09 42.55,19.41 34.29,19.41 v32.38,17.5
MSS_GP_IO_2  (via drill 0.51)
  Top 0.305: v28.57,69.57 P1.P$9
  Route15 0.305: v28.57,69.57 28.57,65.23 arc45 28.65,65.05 29.53,64.17 29.53,51.58 arc45 29.6,51.4 RXTX.3
MSS_GP_IO_3  (via drill 0.51)
  Top 0.305: U$21.P$4 60.03,38.79 60.33,39.09 v60.96,39.09 | v28.57,61.32 P1.P$10
  Bottom 0.305: v60.96,39.09 60.96,38.46 60.64,38.14 49.32,38.14 arc-45 49.14,38.21 48.26,39.09 48.26,60.58 arc45 48.19,60.75 47.62,61.32 v28.57,61.32
MSS_GP_IO_4  (via drill 0.51)
  Top 0.305: v29.84,69.57 P1.P$11
  Route15 0.305: v29.84,69.57 31.64,69.57 arc-45 31.82,69.5 32.38,68.94 32.38,45.55 arc-45 32.31,45.37 SHDN.3
MSS_GP_IO_6  (via drill 0.51)
  Top 0.305: v31.11,65.76 P1.P$14
  Route15 0.305: v31.11,65.76 31.11,56.98 arc-45 31.04,56.8 RXHP.3
N$1  (via drill 0.51)
  Top 0.254: RXHP.1 25.72,58.35 arc-45 25.79,58.53 26.04,58.78 34.19,58.78 arc-45 34.36,58.7 34.92,58.14 34.92,30.94 arc-45 34.85,30.76 33.66,29.57 33.66,20.15 arc-45 33.58,19.97 v32.38,18.77
  Bottom 0.254: U$2.P$12 32.03,30.45 arc-45 32.21,30.38 33.02,29.57 33.02,19.51 arc-45 32.95,19.33 v32.38,18.77
N$2  (via drill 0.51)
  Top 0.305: R3.2 v60.64,22.26 C38.1 | R4.2 v57.78,15.91
  Route15 0.254: v60.64,22.26 60.64,17.18 60.33,16.87 58.42,16.87 57.78,16.23 v57.78,15.91
N$3  (via drill 0.51)
  Top 0.305: R5.1 v61.59,23.53 C44.1 | R6.2 v59.69,15.91
  Route15 0.254: v59.69,15.91 61.28,15.91 61.59,16.23 v61.59,23.53
N$4  (via drill 0.51)
  Top 0.305: R8.2 v59.69,20.68 C46.2 | R9.2 v55.88,15.91
  Route15 0.254: v55.88,15.91 55.88,16.87 56.52,17.5 59.05,17.5 59.69,18.14 v59.69,20.68
N$5
  Top 0.254: T1.P$4 74.55,14.9 75.9,16.25 U$1.P$4
N$6
  Top 0.254: U$1.P$5 76.4,16.12 76.2,15.91 76.2,15.6 76.52,15.28 76.52,14.02 76.2,13.71 T1.P$3 75.96,13.69
N$7  (via drill 0.51)
  Top 0.254: X1.P$1 13.6,43.9 13.97,43.54 13.97,24.49 14.29,24.17 v19.05,24.17
  Bottom 0.254: U$2.P$27 19.38,25.45 19.05,25.12 v19.05,24.17
N$8
  Top 0.254: U$1.P$9 78.4,17.68 79.76,16.33 79.85,16.23 C4.1
N$9
  Top 0.35: T1.P$1 75.87,12.41 71.75,8.29 U$3.SIGNAL
N$10
  Top 0.254: U$1.P$10 78.9,17.81 80.83,15.88 80.83,15.72 C5.1 81.15,15.72
N$11
  Top 0.254: C4.2 79.85,13.1 T2.P$4
N$12
  Top 0.254: C5.2 80.99,13.29 T2.P$3
N$13  (via drill 0.51)
  Top 0.254: v28.57,23.22 28.57,25.12 27.94,25.76 v22.86,25.76
  Bottom 0.254: U$2.P$29 22.06,26.45 arc-45 22.24,26.38 v22.86,25.76 | v28.57,23.22 29.21,22.58 29.21,8.08 arc45 29.28,7.9 29.84,7.34 37.36,7.34 arc-45 37.54,7.27 38.1,6.71 RX/TX.2
N$14
  Top 0.254: R1.1 C17.2 73.34,31.15 | U$1.P$32 76.4,27.14
  Top 0.305: 76.4,27.14 76.4,27.46 74.93,28.93 74.93,29.88 74.61,30.2 73.66,30.2 73.34,30.52 73.34,31.14 C17.2
N$15
  Top 0.35: T2.P$1 81.3,11.77 83.82,9.25 U$4.SIGNAL
N$16  (via drill 0.51, 1.02 pad 1.93)
  Top 0.254: U$1.P$24 81.17,24.7 81.92,25.44 83.27,25.44 C19.1 83.33,25.9 83.82,26.39 85.72,26.39 | R2.1 R1.2 69.85,31.15 v69.53,31.47 | 85.72,26.39 85.72,27.34 v89.53,31.15 | v86.04,26.07 85.72,26.39
  Bottom 0.254: 69.85,31.15 69.85,27.34 71.44,25.76 85.72,25.76 v86.04,26.07
  Bottom 0.305: 69.85,31.15 v69.53,31.47
N$17
  Top 0.254: C18.2 R2.2
N$18
  Top 0.254: U$1.P$28 78.4,27.64 79.8,29.04 C20.2 79.95,29.55 C22.1
N$19
  Top 0.254: C21.1 78.49,29.42 C20.1 78.5,28.69 77.9,28.09 U$1.P$29
N$20
  Top 0.762: U$5.HOT 80.62,32.16 C22.2
N$21
  Top 0.254: U$1.P$33 75.88,25.34
  Top 0.305: U$1.P$33 75.9,27.02 C23.1
N$22
  Top 0.305: C42.2 45.72,22.38 U$6.P$1
N$23
  Bottom 0.254: X1.P$16 7.17,37 6.99,37.19 6.99,44.81 7.3,45.12 13.97,45.12 14.29,44.81 14.29,40.04 14.61,39.73 18.1,39.73 18.41,39.41 18.41,31.47 18.93,30.95 U$2.P$38
N$24
  Top 0.305: U$6.P$25 51.97,19.09 C24.1
N$25  (via drill 0.51)
  Top 0.254: v31.43,29.57 18.52,29.57 arc-45 18.34,29.64 17.78,30.2 17.78,43.43 arc-45 17.85,43.61 CS.1
  Bottom 0.254: U$2.P$13 30.94,29.95 arc-45 31.12,29.88 v31.43,29.57
N$26  (via drill 0.51)
  Top 0.254: SCLK.1 16.19,50.2 15.88,49.89 15.88,30.2 17.14,28.93 30.8,28.93 v31.43,28.3
  Bottom 0.254: U$2.P$14 30.17,29.45 arc-45 30.35,29.38 v31.43,28.3
N$27
  Top 0.305: C30.2 47.64,23 U$6.P$28
N$28  (via drill 0.51)
  Top 0.254: DIN.1 14.92,56.55 14.61,56.24 14.61,29.57 15.88,28.3 30.16,28.3 30.24,28.22 30.32,28.14 v31.43,27.03
  Bottom 0.254: U$2.P$16 29.9,28.45 arc-45 30.08,28.38 v31.43,27.03
N$29  (via drill 0.51)
  Top 0.254: SHDN.1 25.72,45.76 26.04,46.08 31.75,46.08 32.38,45.44 32.38,21.95 30.48,20.04 30.48,19.41 v31.11,18.77
  Bottom 0.254: U$2.P$22 29.52,25.45 29.84,25.12 29.84,19.41 30.48,18.77 v31.11,18.77
N$30  (via drill 0.51)
  Top 0.254: RXTX.1 25.72,52.11 26.04,52.43 33.02,52.43 33.66,51.79 33.66,30.84 33.02,30.2 33.02,21.31 v31.75,20.04
  Bottom 0.254: v31.75,20.04 31.11,20.04 30.48,20.68 30.48,25.44 29.54,26.38 arc45 29.36,26.45 U$2.P$20
N$31
  Top 0.305: C45.2 R7.2 58.42,19.3 58.42,17.5 58.1,17.18 54.61,17.18 53.98,16.55 R10.2
N$32  (via drill 0.51)
  Top 0.254: X1.P$2 12.87,41.14 13.34,40.68 13.34,23.85 13.97,23.22 v17.46,23.22
  Bottom 0.254: v17.46,23.22 17.46,28.93 17.98,29.45 U$2.P$35
N$33
  Bottom 0.254: X1.P$3 16.58,38.38 17.14,37.82 17.14,30.52 17.78,29.88 17.85,29.95 U$2.P$36
N$34
  Bottom 0.254: X1.P$4 16.17,35.62 16.51,35.28 16.51,22.58 16.83,22.26 23.5,22.26 23.81,22.58 23.81,27.98 23.34,28.45 U$2.P$33
N$35
  Bottom 0.254: X1.P$5 15.44,32.86 15.88,32.42 15.88,21.95 16.19,21.63 23.97,21.63 24.29,21.95 24.29,31.79 24.13,31.95 U$2.P$40
N$36
  Bottom 0.254: U$2.P$43 24.37,33.45 24.77,33.06 24.77,21.31 24.45,20.99 15.56,20.99 15.24,21.31 15.24,29.88 15.02,30.1 X1.P$6
N$37
  Bottom 0.254: X1.P$7 14.29,27.34 14.61,27.03 14.61,20.68 14.92,20.36 24.92,20.36 25.24,20.68 25.24,33.69 24.98,33.95 U$2.P$44
N$38
  Bottom 0.254: U$2.P$46 25.41,34.95 25.72,34.65 25.72,20.04 25.4,19.72 14.29,19.72 13.97,20.04 13.97,24.17 13.55,24.58 X1.P$8
N$39
  Bottom 0.254: X1.P$9 13.14,21.82 13.34,21.63 13.34,19.41 13.65,19.09 25.88,19.09 26.19,19.41 26.19,34.8 25.55,35.45 U$2.P$47
N$40
  Bottom 0.254: X1.P$14 13.39,42.52 13.65,42.27 13.65,39.41 13.97,39.09 17.46,39.09 17.78,38.77 17.78,30.84 18.16,30.45 U$2.P$37
N$41  (via drill 0.51)
  Top 0.254: X1.P$15 8.85,39.76 9.84,38.77 9.84,24.17 10.79,23.22 12.7,23.22 13.97,21.95 30.48,21.95 31.43,22.9 v31.43,25.76
  Bottom 0.254: U$2.P$19 30.13,26.95 arc-45 30.31,26.88 v31.43,25.76
N$42
  Top 0.254: U$21.P$6 U$21.P$7
  Top 0.305: U$21.P$5 U$21.P$6
N$43
  Top 0.254: U$14.P$1 62.55,51.47 65.41,48.62 65.41,44.41 U$21.P$24
N$44
  Top 0.254: U$14.P$2 63.82,51.16 66.99,47.98 66.99,44.17 66.67,43.85 66.65,43.88 U$21.P$23
N$45
  Top 0.254: U$14.P$3 65.09,50.84 67.63,48.3 67.63,43.85 67.16,43.38 U$21.P$22
N$46
  Top 0.254: U$14.P$4 66.36,50.52 68.26,48.62 68.26,43.54 67.61,42.88 U$21.P$21
N$47
  Top 0.254: U$14.P$5 67.63,50.2 68.9,48.93 68.9,42.9 68.38,42.38 U$21.P$20
N$48
  Top 0.254: U$14.P$6 68.9,49.89 69.53,49.25 69.53,42.27 69.15,41.88 U$21.P$19
N$49
  Top 0.254: U$14.P$7 70.17,41.63 69.92,41.38 U$21.P$18
N$50
  Top 0.254: U$14.P$8 71.44,41.31 71,40.88 U$21.P$17
N$51
  Top 0.254: U$13.P$8 60.01,51.47 57.15,48.62 57.15,44.41 U$21.P$37
N$52
  Top 0.254: U$13.P$7 58.74,51.16 55.56,47.98 55.56,44.17 55.85,43.88 U$21.P$38
N$53
  Top 0.254: U$13.P$6 57.47,50.84 54.93,48.3 54.93,43.85 55.4,43.38 U$21.P$39
N$54
  Top 0.254: U$13.P$5 56.2,50.52 54.29,48.62 54.29,43.22 54.63,42.88 U$21.P$40
N$55
  Top 0.254: U$13.P$4 54.93,50.2 53.66,48.93 53.66,42.9 54.18,42.38 U$21.P$41
N$56
  Top 0.254: U$13.P$3 53.66,49.89 53.02,49.25 53.02,42.27 53.41,41.88 U$21.P$42
N$57
  Top 0.254: U$13.P$2 52.39,41.95 52.95,41.38 U$21.P$43
N$58
  Top 0.254: U$13.P$1 51.12,41.31 51.55,40.88 U$21.P$44
N$59
  Bottom 0.254: X1.P$17 6.75,34.24 6.35,34.65 6.35,45.44 6.67,45.76 14.61,45.76 14.92,45.44 14.92,40.68 15.24,40.36 18.73,40.36 19.05,40.04 19.05,32.8 19.39,32.45 U$2.P$41
N$60  (via drill 0.51)
  Top 0.305: U$6.P$2 46.04,20.36 v46.35,20.68 | v54.61,19.41 R7.1
  Route15 0.305: v54.61,19.41 47.62,19.41 v46.35,20.68
N$61  (via drill 0.51)
  Top 0.305: v54.61,20.68 R8.1 | U$6.P$3 46.99,19.72 v47.94,20.68
  Route15 0.305: v47.94,20.68 v54.61,20.68
N$62  (via drill 0.51)
  Top 0.254: 52.07,22.58 v51.12,23.53
  Top 0.305: U$6.P$26 51.75,19.72 52.07,20.04 52.07,22.58 | v54.61,23.53 R5.2
  Route15 0.254: 54.29,23.22 51.44,23.22 v51.12,23.53
  Route15 0.305: 54.29,23.22 v54.61,23.53
N$63  (via drill 0.51)
  Top 0.305: U$6.P$27 51.12,20.36 51.44,20.68 51.44,21.95 50.8,22.58 v49.69,22.58 | v54.61,22.26 R3.1
  Route15 0.305: v49.69,22.58 54.29,22.58 v54.61,22.26
N$64
  Top 0.305: R11.2 R17.2 | R11.2 R19.2 R18.2 | R12.2 R13.2 C43.1 64.35,12.42 R11.2
N$65
  Top 0.305: U$21.P$2 59.03,34.2 R14.1
N$66
  Top 0.305: U$21.P$3 59.53,34.39 R15.1
N$67
  Top 0.305: U$21.P$10 63.03,34.39 R16.1
N$68
  Top 0.305: U$21.P$11 63.53,34.2 R20.1
N$69
  Top 0.762: R22.1 C51.1
N$70
  Top 0.762: R21.1 C50.1
RX_I+  (via drill 0.51)
  Top 0.305: v64.14,30.52 R20.2 | U$1.P$38 73,24.2 70.48,26.71 68.26,26.71 67.63,27.34 v67.63,27.66
  Route15 0.305: v67.63,27.66 67.31,27.34 61.91,27.34 61.59,27.66 61.59,29.25 61.91,29.57 63.18,29.57 v64.14,30.52
  Bottom 0.305: v64.14,30.52 64.14,30.68
RX_I-  (via drill 0.51)
  Top 0.305: v62.23,30.52 R16.2 | U$1.P$37 73.45,24.7 70.48,27.66 v68.9,27.66
  Route15 0.305: v68.9,27.66 67.94,26.71 61.59,26.71 60.96,27.34 60.96,30.2 61.28,30.52 v62.23,30.52
RX_Q+
  Top 0.305: U$1.P$36 73.73,25.37 70.48,28.61 59.05,28.61 58.42,29.25 R14.2
RX_Q-
  Top 0.305: U$1.P$35 74.9,26.1 74.61,26.39 73.66,26.39 70.8,29.25 60.01,29.25 59.37,29.88 59.37,30.52 60.33,31.47 R15.2
RXHP  (via drill 0.51)
  Top 0.254: U$1.P$40 72.09,23.2 70.8,24.49 v70.64,24.49
  Bottom 0.254: RXHP.2 28.26,54.01 28.57,53.7 43.81,53.7 44.45,53.06 44.45,30.2 45.09,29.57 56.52,29.57 61.59,24.49 v70.64,24.49
RXTX  (via drill 0.51)
  Top 0.254: 73.66,19.13 U$1.P$48 73.3,18.77 v72.71,18.77 | v72.71,18.77
  Bottom 0.254: v72.71,18.77 72.39,18.14 59.05,18.14 58.42,18.77 58.42,24.17 54.29,28.3 43.18,28.3 42.55,28.93 42.55,46.71 41.91,47.35 28.57,47.35 28.26,47.66 RXTX.2
SCLK  (via drill 0.51)
  Top 0.254: U$1.P$18 81.85,21.7 v82.07,21.47
  Bottom 0.254: SCLK.2 19.37,51.47 19.37,59.41 20,60.05 46.35,60.05 46.99,59.41 46.99,35.28 47.62,34.65 71.12,34.65 71.75,34.01 71.75,27.66 72.39,27.03 73.66,27.03 74.61,27.98 87.63,27.98 88.27,27.34 88.27,22.58 86.68,20.99 82.55,20.99 v82.07,21.47 | v82.07,21.47
SHDN_B  (via drill 0.51)
  Top 0.254: U$1.P$12 80.89,18.52 v81.28,18.14
  Bottom 0.254: v81.28,18.14 80.64,17.5 57.15,17.5 56.52,18.14 56.52,25.12 54.61,27.03 41.27,27.03 40.64,27.66 40.64,37.82 40.01,38.46 28.57,38.46 28.26,38.77 SHDN.2
TX_I+
  Top 0.254: U$1.P$45 69.23,20.7 67.94,19.41 | C45.1 67.94,19.41 | R18.1 68.58,18.77 67.94,19.41
TX_I-  (via drill 0.51)
  Top 0.254: U$1.P$44 69.1,21.2 68.58,20.68 v66.99,20.68 C46.1
  Top 0.305: R19.1 v66.67,15.91
  Route15 0.254: v66.67,15.91 66.67,20.36 v66.99,20.68
TX_Q+  (via drill 0.51)
  Top 0.254: U$1.P$43 69.15,21.7 68.58,22.26 v66.99,22.26 C38.2
  Top 0.305: R11.1 v64.77,15.91
  Route15 0.254: v64.77,15.91 64.77,21.41 C38.2 v66.99,22.26
TX_Q-  (via drill 0.51)
  Top 0.254: U$1.P$42 69.28,22.2 67.94,23.53 v66.99,23.53 C44.2
  Top 0.305: R17.1 v62.87,15.91
  Route15 0.254: v66.99,23.53 63.18,23.53 62.87,23.22 v62.87,15.91
VIN
  pour Top: 14.61,18.14 13.97,17.5 13.97,0.99 14.61,0.36 22.86,0.36 23.5,0.99 23.5,6.07 22.86,6.71 20.95,6.71 20.32,7.34 20.32,17.5 19.68,18.14

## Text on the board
tPlace: 2.85V | 3.3V | RF front-end | Kuo, 08/12 '11 | Rev: 02 | LD | CP | 1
